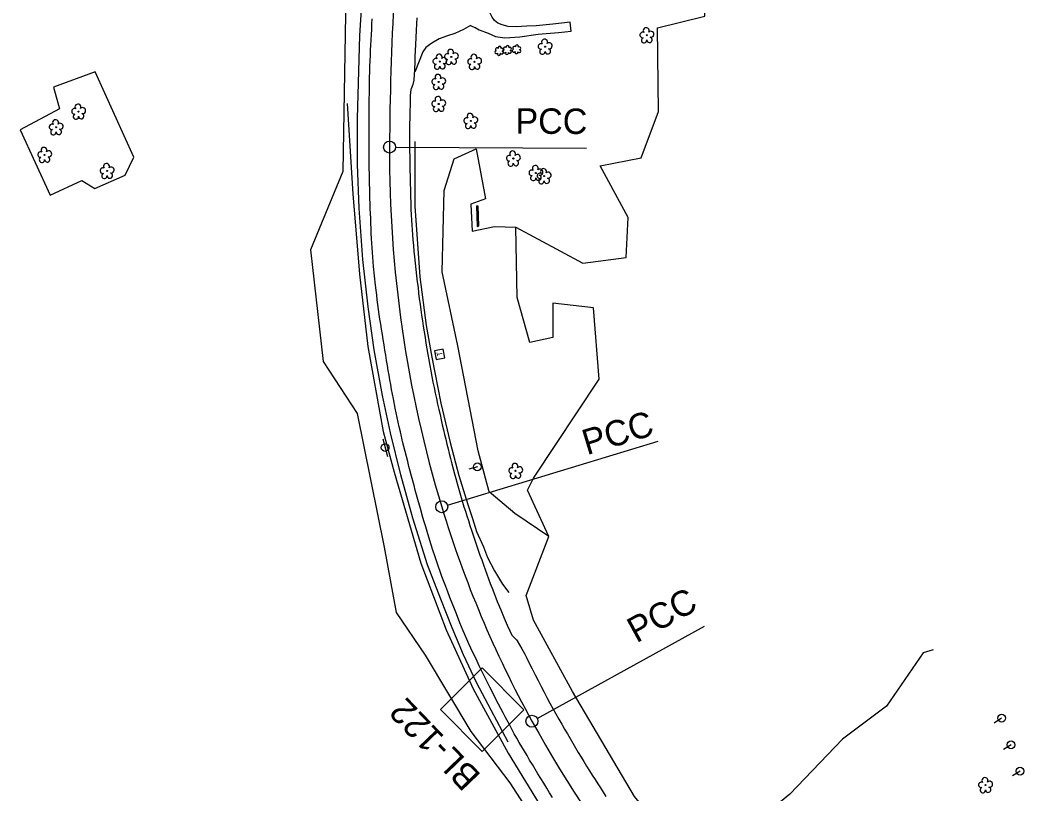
# Model space of a CAD drawing. Extents: x 473158 to 477500, y 500738 to 505114.
# Drawn here: x 474235 to 474866, y 503318 to 503804 of the extents above; entities that cross this region are included whole.
import ezdxf

# ---------------------------------------------------------------- set-up
doc = ezdxf.new("R2010")
doc.units = 0
for name, color, linetype in [('CTL Secondary Horizontal and Vertical CELL', 7, 'Continuous'), ('CTL Secondary Horizontal and Vertical Text', 7, 'Continuous'), ('Exist Guardrail', 7, 'Continuous'), ('Exist Horizontal Alignment', 7, 'Continuous'), ('Exist Roads EOP', 7, 'Continuous'), ('Exist Roads Soil', 7, 'Continuous'), ('Exist Structure Minor Head and End Wall', 7, 'Continuous'), ('Exist Utilities Power Pole CELL', 7, 'Continuous'), ('Exist Utilities Telephone Pedestal CELL', 7, 'Continuous'), ('Exist Utilities Telephone Pole CELL', 7, 'Continuous'), ('Exist Vegetation Hedge Row', 7, 'Continuous'), ('Exist Vegetation Shrub CELL', 7, 'Continuous'), ('Exist Vegetation Tree CELL', 7, 'Continuous'), ('Exist Vegetation Woods Line', 7, 'Continuous')]:
    doc.layers.add(name, color=color, linetype=linetype)

msp = doc.modelspace()

# ---------------------------------------------------------------- linework, layer by layer
at = {"layer": 'CTL Secondary Horizontal and Vertical CELL'}
msp.add_line((474525.29, 503370.73), (474525.29, 503370.73), dxfattribs=at)
msp.add_lwpolyline([(474499.22, 503370.81), (474525.42, 503397.02), (474551.67, 503370.77), (474525.47, 503344.56)], close=True, dxfattribs=at)
at = {"layer": 'Exist Guardrail'}
for points in [[(474448.08, 503685.96), (474447.04, 503713.66), (474447.06, 503742.25), (474447.81, 503772.12), (474448.5, 503794.41), (474450.3, 503824.32), (474452.67, 503858.8), (474454.78, 503886.77), (474456.56, 503912.26), (474458.14, 503935.85)], [(474483.07, 503727.92), (474483.01, 503687.2), (474486.23, 503642.76), (474490.15, 503612.32), (474493.81, 503592.33), (474499.36, 503563.5), (474505.32, 503538.78), (474510.81, 503518.03), (474516.32, 503499.69), (474519.23, 503490.88), (474521.92, 503482.8), (474526.17, 503473.09), (474528.77, 503466.46), (474533.21, 503458.03), (474538.1, 503449.62), (474542.22, 503444.39)], [(474541.64, 503350.31), (474530.98, 503370.4), (474521.81, 503387.8), (474513.7, 503405.22), (474506.48, 503422.24), (474499.36, 503440.26), (474491.1, 503461.78), (474481.79, 503491.2), (474474.32, 503518.32), (474467.78, 503544.87), (474462.67, 503568.32), (474457.45, 503596.97), (474453.66, 503624.06), (474450.42, 503653.61), (474448.08, 503685.96)]]:
    msp.add_lwpolyline(points, dxfattribs=at)
at = {"layer": 'Exist Horizontal Alignment'}
for p, q in [((474470.91, 503724.37), (474590.94, 503723.69)), ((474503.56, 503499.41), (474636.03, 503539.51)), ((474559.99, 503365.34), (474665.17, 503423.18))]:
    msp.add_line(p, q, dxfattribs=at)
for centre in [(474467.16, 503724.39), (474499.97, 503498.32), (474556.7, 503363.53)]:
    msp.add_circle(centre, 3.75, dxfattribs=at)
for centre, radius, start, end in [((476415.56, 503713.38), 1948.44, 174.05611, 179.67611), ((475232.44, 503720.06), 765.3, 179.67611, 196.84305), ((475171.39, 503701.58), 701.51, 196.84305, 208.80885), ((475209.24, 503722.4), 744.7, 208.80885, 230.08898)]:
    msp.add_arc(centre, radius, start, end, dxfattribs=at)
at = {"layer": 'Exist Roads EOP'}
for points in [[(474569.61, 503315.68), (474567.8, 503318.58), (474565.98, 503321.53), (474564.14, 503324.51), (474562.3, 503327.53), (474560.47, 503330.53), (474558.68, 503333.46), (474556.95, 503336.33), (474555.26, 503339.12), (474553.6, 503341.88), (474551.95, 503344.65), (474550.32, 503347.43), (474548.7, 503350.22), (474547.12, 503352.98), (474545.6, 503355.69), (474542.74, 503360.95), (474539.95, 503366.18), (474538.53, 503368.85), (474537.1, 503371.57), (474535.67, 503374.3), (474534.26, 503377.01), (474532.87, 503379.69), (474530.17, 503385.01), (474527.5, 503390.34), (474524.87, 503395.72), (474523.56, 503398.44), (474522.25, 503401.17), (474520.94, 503403.91), (474519.63, 503406.67), (474518.35, 503409.44), (474517.08, 503412.22), (474515.83, 503415.02), (474513.48, 503420.43), (474511.41, 503425.46), (474509.24, 503430.93), (474507.97, 503434.14), (474506.58, 503437.67), (474505.16, 503441.29), (474503.8, 503444.79), (474502.51, 503448.17), (474501.29, 503451.42), (474500.12, 503454.57), (474499.02, 503457.61), (474497.97, 503460.57), (474496.03, 503466.22), (474494.23, 503471.71), (474492.54, 503477.12), (474490.8, 503482.81), (474489.9, 503485.77), (474489.01, 503488.75), (474488.15, 503491.66), (474486.53, 503497.3), (474484.95, 503502.91), (474484.16, 503505.79), (474483.35, 503508.72), (474482.55, 503511.68), (474481.74, 503514.65), (474480.95, 503517.63), (474480.15, 503520.63), (474479.36, 503523.65), (474478.56, 503526.72), (474477.76, 503529.84), (474476.96, 503533), (474476.17, 503536.17), (474475.41, 503539.31), (474474.66, 503542.42), (474473.95, 503545.49), (474473.26, 503548.53), (474472.6, 503551.53), (474471.96, 503554.49), (474470.78, 503560.34), (474469.62, 503566.21), (474469.04, 503569.16), (474468.48, 503572.11), (474467.93, 503575.07), (474467.4, 503578.03), (474466.89, 503580.98), (474466.38, 503583.98), (474465.87, 503587.07), (474465.34, 503590.25), (474464.81, 503593.52), (474464.27, 503596.82), (474463.73, 503600.11), (474463.19, 503603.37), (474462.65, 503606.61), (474462.13, 503609.83), (474461.62, 503613), (474461.14, 503616.13), (474460.68, 503619.22), (474460.25, 503622.29), (474459.83, 503625.36), (474459.44, 503628.42), (474459.07, 503631.48), (474458.71, 503634.52), (474458.38, 503637.52), (474457.75, 503643.42), (474457.17, 503649.25), (474456.64, 503655.09), (474456.17, 503660.99), (474455.99, 503663.99), (474455.83, 503667.01), (474455.69, 503670.07), (474455.56, 503673.17), (474455.43, 503676.31), (474455.31, 503679.49), (474455.19, 503682.68), (474455.08, 503685.84), (474454.97, 503688.96), (474454.87, 503692.06), (474454.77, 503695.14), (474454.68, 503698.22), (474454.61, 503701.31), (474454.54, 503704.4), (474454.48, 503707.52), (474454.43, 503710.67), (474454.39, 503713.87), (474454.36, 503717.11), (474454.34, 503720.4), (474454.32, 503723.74), (474454.31, 503727.13), (474454.3, 503730.56), (474454.3, 503734.02), (474454.3, 503737.49), (474454.31, 503740.96), (474454.33, 503744.44), (474454.35, 503747.9), (474454.38, 503751.32), (474454.42, 503754.7), (474454.46, 503758.04), (474454.51, 503761.39), (474454.58, 503764.77), (474454.65, 503768.19), (474454.74, 503771.65), (474454.84, 503775.1), (474454.95, 503778.51), (474455.09, 503781.86), (474455.24, 503785.17), (474455.41, 503788.45), (474455.58, 503791.73), (474455.76, 503795.02), (474455.94, 503798.3), (474456.13, 503801.61), (474456.32, 503804.96)], [(474484.34, 503805.69), (474484.15, 503801.83), (474483.95, 503797.7), (474483.74, 503793.29), (474483.53, 503788.93), (474483.34, 503784.94), (474483.16, 503781.32), (474483.01, 503778.07), (474482.78, 503772.99), (474482.66, 503770.01), (474482.34, 503766.37), (474481.79, 503763.65), (474480.75, 503760.88), (474480.63, 503760.45), (474480.23, 503756.69), (474480.04, 503751.63), (474479.92, 503746.16), (474479.86, 503742.68), (474479.81, 503738.71), (474479.78, 503734.52), (474479.76, 503730.37), (474479.77, 503726.26), (474479.79, 503722.21), (474479.83, 503718.16), (474479.89, 503714.08), (474479.97, 503709.96), (474480.06, 503705.81), (474480.16, 503701.66), (474480.26, 503697.52), (474480.38, 503693.4), (474480.49, 503689.29), (474480.62, 503685.35), (474480.77, 503681.71), (474480.94, 503678.38), (474481.12, 503675.34), (474481.33, 503672.38), (474481.57, 503669.27), (474481.84, 503666), (474482.14, 503662.57), (474482.47, 503659), (474482.84, 503655.3), (474483.26, 503651.47), (474483.71, 503647.5), (474484.18, 503643.54), (474484.63, 503639.72), (474485.06, 503636.05), (474485.47, 503632.52), (474485.89, 503629.07), (474486.34, 503625.61), (474486.81, 503622.15), (474487.31, 503618.69), (474487.83, 503615.21), (474488.36, 503611.71), (474488.9, 503608.17), (474489.46, 503604.6), (474490.03, 503601.04), (474490.61, 503597.52), (474491.2, 503594.04), (474491.81, 503590.6), (474492.44, 503587.17), (474493.08, 503583.71), (474493.75, 503580.22), (474494.43, 503576.7), (474495.14, 503573.19), (474495.86, 503569.72), (474496.61, 503566.28), (474497.38, 503562.89), (474498.15, 503559.54), (474498.9, 503556.26), (474499.63, 503553.03), (474500.35, 503549.87), (474501.05, 503546.76), (474501.76, 503543.7), (474502.48, 503540.69), (474503.21, 503537.72), (474503.96, 503534.74), (474504.73, 503531.69), (474505.53, 503528.57), (474506.36, 503525.39), (474507.2, 503522.2), (474508.03, 503519.06), (474508.86, 503515.97), (474509.68, 503512.93), (474510.51, 503509.94), (474511.35, 503506.99), (474512.2, 503504.07), (474513.07, 503501.2), (474513.95, 503498.33), (474514.86, 503495.44), (474515.78, 503492.52), (474516.73, 503489.58), (474517.7, 503486.6), (474518.7, 503483.56), (474519.74, 503480.45), (474520.8, 503477.29), (474521.88, 503474.12), (474522.96, 503470.99), (474524.03, 503467.92), (474525.1, 503464.89), (474526.17, 503461.89), (474527.25, 503458.91), (474528.33, 503455.94), (474529.42, 503452.99), (474530.51, 503450.07), (474531.6, 503447.19), (474532.69, 503444.36), (474534.88, 503438.82), (474537.07, 503433.44), (474539.23, 503428.3), (474541.18, 503423.86), (474542.83, 503420.29), (474544.1, 503417.71), (474544.29, 503417.42), (474544.81, 503416.78), (474546.88, 503414.63), (474547.41, 503413.98), (474550.31, 503409.11), (474552.16, 503405.61), (474553.44, 503403.13), (474554.98, 503400.11), (474556.77, 503396.55), (474558.68, 503392.77), (474560.57, 503389.07), (474562.44, 503385.44), (474564.28, 503381.89), (474566.12, 503378.39), (474567.98, 503374.93), (474569.85, 503371.51), (474571.74, 503368.13), (474573.62, 503364.82), (474575.45, 503361.61), (474577.23, 503358.51), (474578.97, 503355.52), (474580.68, 503352.59), (474582.4, 503349.67), (474584.12, 503346.77), (474585.85, 503343.88), (474587.58, 503341), (474589.33, 503338.14), (474591.08, 503335.27), (474592.85, 503332.42), (474594.61, 503329.6), (474596.35, 503326.86), (474598.05, 503324.19), (474599.72, 503321.59), (474601.42, 503318.98), (474603.21, 503316.28)]]:
    msp.add_lwpolyline(points, dxfattribs=at)
at = {"layer": 'Exist Roads Soil'}
for points in [[(474517.99, 503800.68), (474519.38, 503800.1), (474521.04, 503799.45), (474523.44, 503798.14), (474529.1, 503795.95), (474533.69, 503793.96), (474539.74, 503793.01), (474549.11, 503793.58), (474560.58, 503795.23), (474573.42, 503796.48), (474581.44, 503797.23), (474580.76, 503802.78), (474569.86, 503801.64), (474559.4, 503800.51), (474553.46, 503800.27), (474546.75, 503799.92), (474541.65, 503800.24), (474537.98, 503801.17), (474535.29, 503802.27), (474533.22, 503803.9), (474531.77, 503806.01), (474530.44, 503808.57), (474530.1, 503810.09), (474529.8, 503812.44)], [(474517.99, 503800.68), (474513.76, 503798.25), (474508.25, 503795.73), (474503.59, 503794.22), (474498.44, 503792.4), (474493.83, 503789.6), (474490.03, 503786.99), (474488, 503784.27), (474483.07, 503771.49)]]:
    msp.add_lwpolyline(points, dxfattribs=at)
at = {"layer": 'Exist Structure Minor Head and End Wall'}
for p, q in [((474521.8, 503687.49), (474522.63, 503687.51)), ((474521.8, 503687.49), (474522.15, 503674.54)), ((474522.63, 503687.51), (474522.99, 503674.56)), ((474522.15, 503674.54), (474522.99, 503674.56))]:
    msp.add_line(p, q, dxfattribs=at)
at = {"layer": 'Exist Utilities Power Pole CELL'}
for p, q in [((474522.38, 503523.37), (474516.94, 503521.93)), ((474522.38, 503523.37), (474522.38, 503523.37)), ((474851.97, 503365.48), (474847.33, 503362.3)), ((474851.97, 503365.48), (474851.97, 503365.48)), ((474857.91, 503348.68), (474853.09, 503345.77)), ((474857.91, 503348.68), (474857.91, 503348.68)), ((474863.56, 503332.14), (474858.73, 503329.26)), ((474863.56, 503332.14), (474863.56, 503332.14))]:
    msp.add_line(p, q, dxfattribs=at)
for centre in [(474522.38, 503523.37), (474851.97, 503365.48), (474857.91, 503348.68), (474863.56, 503332.14)]:
    msp.add_circle(centre, 2.45, dxfattribs=at)
at = {"layer": 'Exist Utilities Telephone Pedestal CELL'}
msp.add_line((474498.67, 503594.06), (474498.67, 503594.06), dxfattribs=at)
msp.add_lwpolyline([(474501.94, 503591.89), (474500.93, 503597.4), (474495.43, 503596.39), (474496.43, 503590.89), (474501.94, 503591.89)], dxfattribs=at)
at = {"layer": 'Exist Utilities Telephone Pole CELL'}
for p, q in [((474463.01, 503540.99), (474465.81, 503530)), ((474464.41, 503535.49), (474464.41, 503535.49))]:
    msp.add_line(p, q, dxfattribs=at)
msp.add_circle((474464.41, 503535.49), 2.41, dxfattribs=at)
at = {"layer": 'Exist Vegetation Hedge Row'}
msp.add_line((474440.61, 503751.82), (474444.08, 503695.01), dxfattribs=at)
for points in [[(474567.39, 503479.54), (474546.04, 503493.98), (474529.79, 503507.6), (474522.81, 503533.37), (474510.12, 503599.4), (474500.23, 503645.9), (474501.47, 503697.16), (474507.79, 503716.96), (474521.71, 503723.27), (474527.44, 503691.88), (474518.35, 503688.4), (474519.09, 503671.44), (474533.18, 503674.41), (474546.56, 503674.1)], [(474444.08, 503695.01), (474448.37, 503644.42), (474453.53, 503599.09), (474463.11, 503545.53), (474470.08, 503520.03), (474486.91, 503462.77), (474502.84, 503421.03), (474519.79, 503383.9), (474541.73, 503343.5), (474572.12, 503293.76), (474601.46, 503255.5), (474633.21, 503214.89)]]:
    msp.add_lwpolyline(points, dxfattribs=at)
at = {"layer": 'Exist Vegetation Shrub CELL'}
for p, q in [((474536.13, 503784.68), (474536.13, 503784.68)), ((474541.17, 503785.19), (474541.17, 503785.19)), ((474547.05, 503785.6), (474547.05, 503785.6))]:
    msp.add_line(p, q, dxfattribs=at)
for centre, radius, start, end in [((474536.36, 503786.72), 0.99, 334.83907, 200.47174), ((474539.69, 503786.32), 0.968, 35.89076, 245.42165), ((474541.4, 503787.23), 0.99, 334.83907, 200.47174), ((474545.57, 503786.72), 0.968, 35.89076, 245.42165), ((474547.28, 503787.64), 0.99, 334.83907, 200.47174), ((474548.72, 503786.46), 0.929, 284.45672, 126.08612), ((474534.33, 503783.98), 0.955, 95.10992, 327.95341), ((474534.65, 503785.81), 0.968, 35.89076, 245.42165), ((474536, 503783), 0.984, 151.27966, 21.38702), ((474537.77, 503783.75), 0.937, 204.99133, 73.46012), ((474537.8, 503785.55), 0.929, 284.45672, 126.08612), ((474539.37, 503784.49), 0.955, 95.10992, 327.95341), ((474541.04, 503783.51), 0.984, 151.27966, 21.38702), ((474542.81, 503784.26), 0.937, 204.99133, 73.46012), ((474542.84, 503786.06), 0.929, 284.45672, 126.08612), ((474545.25, 503784.89), 0.955, 95.10992, 327.95341), ((474546.92, 503783.91), 0.984, 151.27966, 21.38702), ((474548.69, 503784.67), 0.937, 204.99133, 73.46012)]:
    msp.add_arc(centre, radius, start, end, dxfattribs=at)
at = {"layer": 'Exist Vegetation Tree CELL'}
for p, q in [((474628.92, 503794.67), (474628.92, 503794.67)), ((474564.98, 503787.47), (474564.98, 503787.47)), ((474506, 503781.05), (474506, 503781.05)), ((474498.75, 503778.09), (474498.75, 503778.09)), ((474520.6, 503777.94), (474520.6, 503777.94)), ((474498.03, 503765.32), (474498.03, 503765.32)), ((474498.05, 503751.45), (474498.05, 503751.45)), ((474271.64, 503746.67), (474271.64, 503746.67)), ((474257.54, 503736.86), (474257.54, 503736.86)), ((474518.22, 503740.82), (474518.22, 503740.82)), ((474250.31, 503719.48), (474250.31, 503719.48)), ((474545, 503717.19), (474545, 503717.19)), ((474289.57, 503709.36), (474289.57, 503709.36)), ((474559.19, 503708.06), (474559.19, 503708.06)), ((474564.33, 503706.13), (474564.33, 503706.13)), ((474546.43, 503520.88), (474546.43, 503520.88)), ((474841.87, 503323.36), (474841.87, 503323.36))]:
    msp.add_line(p, q, dxfattribs=at)
for centre in [(474628.92, 503794.67), (474564.98, 503787.47), (474506, 503781.05), (474498.75, 503778.09), (474520.6, 503777.94), (474498.03, 503765.32), (474498.05, 503751.45), (474271.64, 503746.67), (474257.54, 503736.86), (474518.22, 503740.82), (474250.31, 503719.48), (474545, 503717.19), (474289.57, 503709.36), (474559.19, 503708.06), (474564.33, 503706.13), (474546.43, 503520.88), (474841.87, 503323.36)]:
    msp.add_circle(centre, 0.326, dxfattribs=at)
for centre, radius, start, end in [((474626.31, 503794.83), 1.73, 62.66361, 279.3457), ((474628.53, 503797.55), 1.86, 330.16508, 219.71335), ((474630.59, 503791.77), 1.7, 181.28216, 74.55999), ((474631.47, 503795.26), 1.9, 257.1011, 134.19993), ((474562.37, 503787.63), 1.73, 62.66361, 279.3457), ((474564.59, 503790.35), 1.86, 330.16508, 219.71335), ((474567.53, 503788.06), 1.9, 257.1011, 134.19993), ((474627.21, 503791.55), 1.69, 111.56708, 6.23104), ((474498.36, 503780.96), 1.86, 330.16508, 219.71335), ((474503.4, 503781.2), 1.73, 62.66361, 279.3457), ((474505.62, 503783.92), 1.86, 330.16508, 219.71335), ((474508.55, 503781.63), 1.9, 257.1011, 134.19993), ((474520.22, 503780.81), 1.86, 330.16508, 219.71335), ((474563.27, 503784.35), 1.69, 111.56708, 6.23104), ((474566.65, 503784.57), 1.7, 181.28216, 74.55999), ((474496.14, 503778.24), 1.73, 62.66361, 279.3457), ((474497.04, 503774.97), 1.69, 111.56708, 6.23104), ((474500.42, 503775.19), 1.7, 181.28216, 74.55999), ((474501.3, 503778.68), 1.9, 257.1011, 134.19993), ((474504.3, 503777.92), 1.69, 111.56708, 6.23104), ((474507.68, 503778.15), 1.7, 181.28216, 74.55999), ((474518, 503778.09), 1.73, 62.66361, 279.3457), ((474518.9, 503774.82), 1.69, 111.56708, 6.23104), ((474522.28, 503775.04), 1.7, 181.28216, 74.55999), ((474523.15, 503778.53), 1.9, 257.1011, 134.19993), ((474497.64, 503768.2), 1.86, 330.16508, 219.71335), ((474495.42, 503765.48), 1.73, 62.66361, 279.3457), ((474496.32, 503762.2), 1.69, 111.56708, 6.23104), ((474499.7, 503762.42), 1.7, 181.28216, 74.55999), ((474500.58, 503765.91), 1.9, 257.1011, 134.19993), ((474497.67, 503754.33), 1.86, 330.16508, 219.71335), ((474271.26, 503749.55), 1.86, 330.16508, 219.71335), ((474495.45, 503751.61), 1.73, 62.66361, 279.3457), ((474496.35, 503748.33), 1.69, 111.56708, 6.23104), ((474499.73, 503748.55), 1.7, 181.28216, 74.55999), ((474500.6, 503752.04), 1.9, 257.1011, 134.19993), ((474269.03, 503746.83), 1.73, 62.66361, 279.3457), ((474269.94, 503743.55), 1.69, 111.56708, 6.23104), ((474273.31, 503743.77), 1.7, 181.28216, 74.55999), ((474274.19, 503747.26), 1.9, 257.1011, 134.19993), ((474517.83, 503743.7), 1.86, 330.16508, 219.71335), ((474520.77, 503741.41), 1.9, 257.1011, 134.19993), ((474254.93, 503737.02), 1.73, 62.66361, 279.3457), ((474257.15, 503739.74), 1.86, 330.16508, 219.71335), ((474260.08, 503737.45), 1.9, 257.1011, 134.19993), ((474515.61, 503740.98), 1.73, 62.66361, 279.3457), ((474516.51, 503737.7), 1.69, 111.56708, 6.23104), ((474519.89, 503737.92), 1.7, 181.28216, 74.55999), ((474255.83, 503733.74), 1.69, 111.56708, 6.23104), ((474259.21, 503733.96), 1.7, 181.28216, 74.55999), ((474249.93, 503722.35), 1.86, 330.16508, 219.71335), ((474247.71, 503719.63), 1.73, 62.66361, 279.3457), ((474248.61, 503716.36), 1.69, 111.56708, 6.23104), ((474251.99, 503716.58), 1.7, 181.28216, 74.55999), ((474252.86, 503720.07), 1.9, 257.1011, 134.19993), ((474542.39, 503717.35), 1.73, 62.66361, 279.3457), ((474544.61, 503720.07), 1.86, 330.16508, 219.71335), ((474547.55, 503717.78), 1.9, 257.1011, 134.19993), ((474289.18, 503712.23), 1.86, 330.16508, 219.71335), ((474292.12, 503709.95), 1.9, 257.1011, 134.19993), ((474543.29, 503714.07), 1.69, 111.56708, 6.23104), ((474546.67, 503714.29), 1.7, 181.28216, 74.55999), ((474558.81, 503710.93), 1.86, 330.16508, 219.71335), ((474286.96, 503709.51), 1.73, 62.66361, 279.3457), ((474287.86, 503706.24), 1.69, 111.56708, 6.23104), ((474291.24, 503706.46), 1.7, 181.28216, 74.55999), ((474556.59, 503708.21), 1.73, 62.66361, 279.3457), ((474557.49, 503704.94), 1.69, 111.56708, 6.23104), ((474560.86, 503705.16), 1.7, 181.28216, 74.55999), ((474561.73, 503706.28), 1.73, 62.66361, 279.3457), ((474561.74, 503708.65), 1.9, 257.1011, 134.19993), ((474563.95, 503709), 1.86, 330.16508, 219.71335), ((474566.88, 503706.72), 1.9, 257.1011, 134.19993), ((474562.63, 503703.01), 1.69, 111.56708, 6.23104), ((474566.01, 503703.23), 1.7, 181.28216, 74.55999), ((474543.82, 503521.03), 1.73, 62.66361, 279.3457), ((474546.04, 503523.75), 1.86, 330.16508, 219.71335), ((474548.98, 503521.47), 1.9, 257.1011, 134.19993), ((474544.72, 503517.76), 1.69, 111.56708, 6.23104), ((474548.1, 503517.98), 1.7, 181.28216, 74.55999), ((474841.49, 503326.23), 1.86, 330.16508, 219.71335), ((474839.26, 503323.51), 1.73, 62.66361, 279.3457), ((474840.17, 503320.24), 1.69, 111.56708, 6.23104), ((474843.54, 503320.46), 1.7, 181.28216, 74.55999), ((474844.42, 503323.95), 1.9, 257.1011, 134.19993)]:
    msp.add_arc(centre, radius, start, end, dxfattribs=at)
at = {"layer": 'Exist Vegetation Woods Line'}
for points in [[(474494.78, 504312.62), (474476.79, 504178.44), (474459.77, 504087.31), (474441.83, 503933.16), (474440.33, 503857.37), (474437.89, 503709.04), (474417.41, 503659.72)], [(474635.55, 503799.27), (474665.43, 503806.64), (474665.4, 503829.84), (474708.52, 503839.82), (474708.64, 503839.85)], [(474546.56, 503674.1), (474588.78, 503651.41), (474616.02, 503654.98), (474617.1, 503680.16), (474599.62, 503712.48), (474625.42, 503717.64), (474636.29, 503746.71), (474635.55, 503799.27)], [(474306.42, 503718.03), (474282.05, 503771.74), (474255.83, 503761.95), (474259.67, 503748.46), (474234.88, 503735.1), (474253.74, 503694.09), (474273.65, 503703.33), (474281.79, 503698.29), (474300.86, 503706.77), (474306.42, 503718.03)], [(474808.93, 503408.32), (474802.62, 503406.43), (474779.61, 503372.89), (474751.89, 503352.19), (474718.75, 503317.67), (474664.37, 503272.8), (474657.63, 503273.56), (474655.3, 503274.92), (474621.17, 503316.29), (474582.13, 503382.19), (474557.68, 503427.09), (474553.06, 503442.52), (474567.39, 503479.54), (474553.83, 503508.83), (474557.7, 503516.31), (474598.96, 503578.51), (474595.47, 503623.36), (474569.88, 503626.18), (474569.75, 503604.61), (474555.47, 503601.48), (474547.44, 503629.91), (474546.56, 503674.1)], [(474417.41, 503659.72), (474425.49, 503589.6), (474446.84, 503556.89), (474463.81, 503473.01), (474471.33, 503431.8), (474489.58, 503404.95), (474518.23, 503357.05), (474542.86, 503324.75), (474589.83, 503252.15), (474559.03, 503227.36), (474517.97, 503186.35), (474479.83, 503176.32), (474442.79, 503153.41), (474424.74, 503138.06), (474392.94, 503125.22), (474370.72, 503110.81), (474316.94, 503083.12), (474290.87, 503062.45)]]:
    msp.add_lwpolyline(points, dxfattribs=at)

# ---------------------------------------------------------------- texts
at = {"layer": 'CTL Secondary Horizontal and Vertical Text'}
msp.add_text('BL-122', height=16, rotation=133.87228, dxfattribs=at).set_placement((474525.28, 503329.61))
at = {"layer": 'Exist Horizontal Alignment'}
for rotation, p in [(359.67611, (474546.3, 503732.8)), (16.84305, (474591.23, 503530.65)), (28.80885, (474622.39, 503412.39))]:
    msp.add_text('PCC', height=16, rotation=rotation, dxfattribs=at).set_placement(p)
at = {"layer": 'Exist Utilities Telephone Pedestal CELL'}
msp.add_text('T', height=3.42, rotation=100.37733, dxfattribs=at).set_placement((474500.56, 503593.26))

doc.saveas('drawing.dxf')
